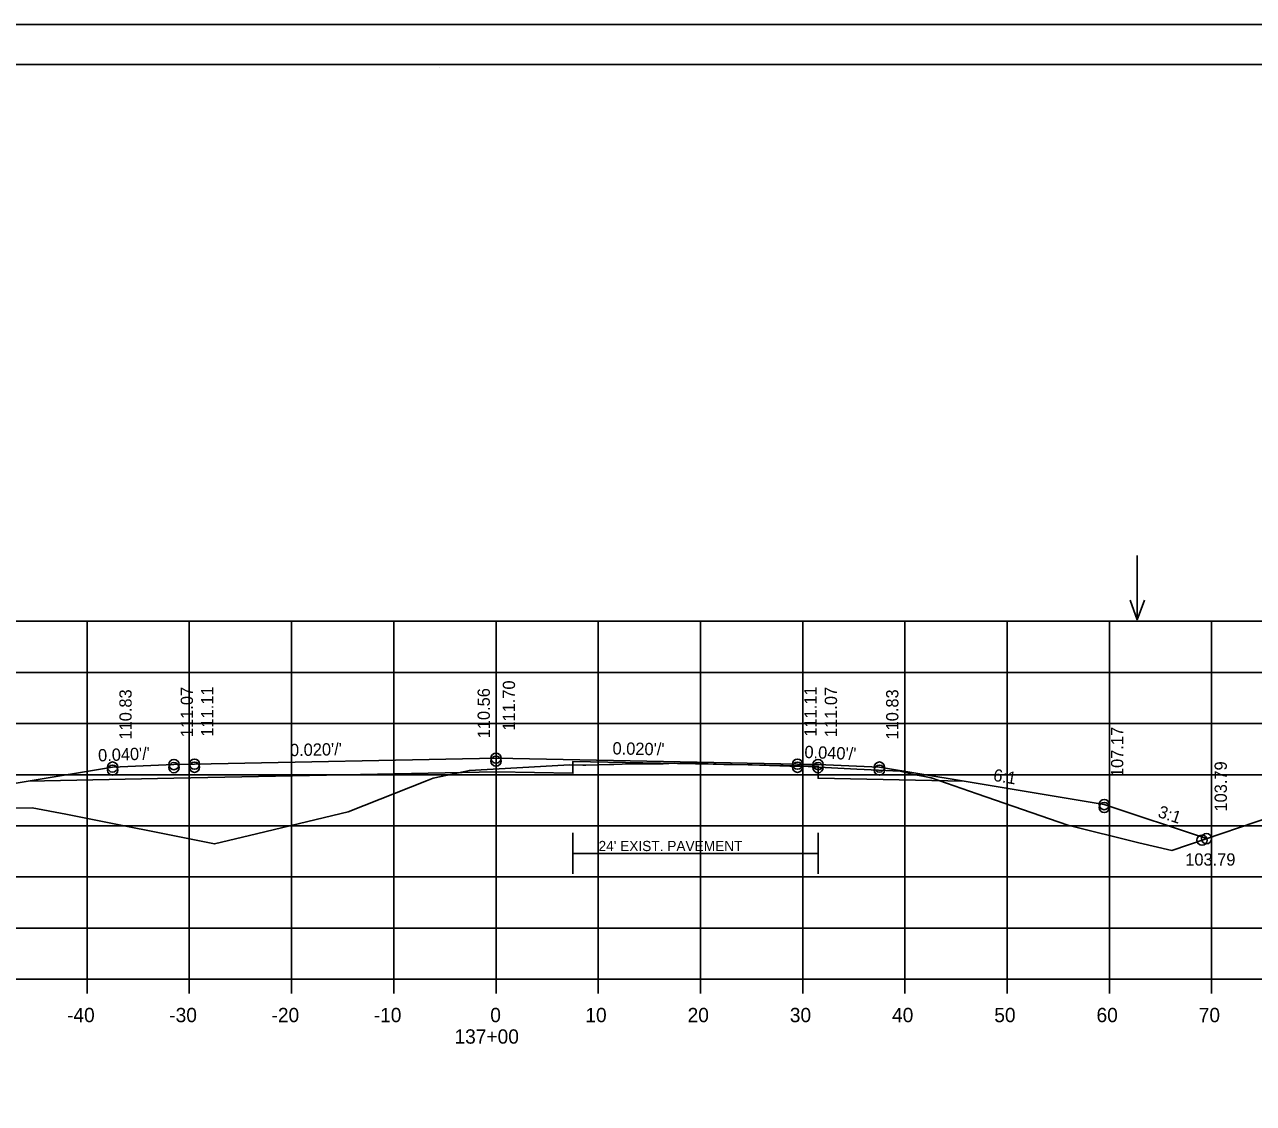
# Model space of a CAD drawing. Extents: x 1175611 to 1176402, y -433344 to -416213.
# Drawn here: x 1175734.9 to 1175855.1, y -430249 to -430143.5 of the extents above; entities that cross this region are included whole.
import ezdxf

# ---------------------------------------------------------------- set-up
doc = ezdxf.new("R2010")
doc.units = 0
for name, color, linetype in [('R_Alt Surface', 7, 'Continuous'), ('R_Axis', 7, 'Continuous'), ('R_Axis Annot', 7, 'Continuous'), ('R_Border', 7, 'Continuous'), ('R_Draft', 7, 'Continuous'), ('R_Exist Surface', 7, 'Continuous'), ('R_Fin Surface', 7, 'Continuous'), ('R_Grid', 7, 'Continuous'), ('R_No Plot', 7, 'Continuous'), ('R_Water Annot', 7, 'Continuous'), ('R_Xsect Elev', 7, 'Continuous'), ('R_Xsect Slope', 7, 'Continuous')]:
    doc.layers.add(name, color=color, linetype=linetype)

msp = doc.modelspace()

# ---------------------------------------------------------------- linework, layer by layer
at = {"layer": 'R_Alt Surface'}
msp.add_lwpolyline([(1175735.2, -430217.45), (1175749.47, -430217.17), (1175780.97, -430216.53), (1175788.49, -430216.68), (1175788.49, -430215.52), (1175812.49, -430216), (1175812.47, -430217.17), (1175826.75, -430217.45)], dxfattribs=at)
at = {"layer": 'R_Axis'}
for p, q in [((1175640.97, -430236.82), (1175920.97, -430236.82)), ((1175740.97, -430238.22), (1175740.97, -430236.82)), ((1175750.97, -430238.22), (1175750.97, -430236.82)), ((1175760.97, -430238.22), (1175760.97, -430236.82)), ((1175770.97, -430238.22), (1175770.97, -430236.82)), ((1175780.97, -430238.22), (1175780.97, -430236.82)), ((1175790.97, -430238.22), (1175790.97, -430236.82)), ((1175800.97, -430238.22), (1175800.97, -430236.82)), ((1175810.97, -430238.22), (1175810.97, -430236.82)), ((1175820.97, -430238.22), (1175820.97, -430236.82)), ((1175830.97, -430238.22), (1175830.97, -430236.82)), ((1175840.97, -430238.22), (1175840.97, -430236.82)), ((1175850.97, -430238.22), (1175850.97, -430236.82))]:
    msp.add_line(p, q, dxfattribs=at)
at = {"layer": 'R_Border'}
for p, q in [((1175622.97, -430147.36), (1175939.15, -430147.36)), ((1175775.49, -430147.62), (1175775.49, -430147.62)), ((1175775.49, -430147.62), (1175775.49, -430147.62))]:
    msp.add_line(p, q, dxfattribs=at)
at = {"layer": 'R_Draft'}
for q in [(1175788.49, -430224.51), (1175812.49, -430224.51)]:
    msp.add_line((1175800.49, -430224.51), q, dxfattribs=at)
for points in [[(1175788.49, -430226.51), (1175788.49, -430222.51)], [(1175812.49, -430226.51), (1175812.49, -430222.51)]]:
    msp.add_lwpolyline(points, dxfattribs=at)
at = {"layer": 'R_Exist Surface'}
msp.add_lwpolyline([(1175690.55, -430220.08), (1175735.61, -430220.06), (1175738.89, -430220.67), (1175753.43, -430223.58), (1175756.85, -430222.78), (1175766.52, -430220.46), (1175774.17, -430217.43), (1175774.83, -430217.16), (1175775.59, -430217), (1175777.76, -430216.53), (1175778.37, -430216.4), (1175780.12, -430216.31), (1175784.18, -430216.08), (1175788.16, -430215.85), (1175789.46, -430215.88), (1175789.77, -430215.89), (1175792.08, -430215.82), (1175792.5, -430215.81), (1175793.32, -430215.8), (1175797.1, -430215.75), (1175797.31, -430215.74), (1175798.46, -430215.7), (1175798.71, -430215.71), (1175799.53, -430215.71), (1175800.68, -430215.73), (1175800.97, -430215.73), (1175803.27, -430215.81), (1175803.77, -430215.82), (1175804.06, -430215.82), (1175806.03, -430215.85), (1175806.76, -430215.88), (1175809.7, -430215.97), (1175809.96, -430215.97), (1175810.98, -430215.99), (1175812.54, -430216.07), (1175816.28, -430216.27), (1175820.49, -430216.48), (1175821.82, -430216.79), (1175822.9, -430217.01), (1175823.54, -430217.14), (1175828.03, -430218.69), (1175836.9, -430221.77), (1175843.86, -430223.47), (1175847.09, -430224.22), (1175858.58, -430220.33)], dxfattribs=at)
at = {"layer": 'R_Fin Surface'}
msp.add_lwpolyline([(1175686.73, -430220.07), (1175703.6, -430225.7), (1175721.47, -430219.74), (1175735.2, -430217.45), (1175743.47, -430216.07), (1175749.47, -430215.83), (1175751.47, -430215.79), (1175780.97, -430215.2), (1175810.47, -430215.79), (1175812.47, -430215.83), (1175818.47, -430216.07), (1175826.75, -430217.45), (1175840.47, -430219.74), (1175850.47, -430223.07)], dxfattribs=at)
msp.add_lwpolyline([(1175686.73, -430220.07), (1175703.6, -430225.7), (1175721.47, -430219.74), (1175735.2, -430217.45), (1175743.47, -430216.07), (1175749.47, -430215.83), (1175751.47, -430215.79), (1175780.97, -430215.2), (1175810.47, -430215.79), (1175812.47, -430215.83), (1175818.47, -430216.07), (1175826.75, -430217.45), (1175840.47, -430219.74), (1175850.47, -430223.07)], dxfattribs=at)
at = {"layer": 'R_Grid'}
for p, q in [((1175640.97, -430201.82), (1175920.97, -430201.82)), ((1175740.97, -430236.82), (1175740.97, -430201.82)), ((1175750.97, -430236.82), (1175750.97, -430201.82)), ((1175760.97, -430236.82), (1175760.97, -430201.82)), ((1175770.97, -430236.82), (1175770.97, -430201.82)), ((1175780.97, -430236.82), (1175780.97, -430201.82)), ((1175790.97, -430236.82), (1175790.97, -430201.82)), ((1175800.97, -430236.82), (1175800.97, -430201.82)), ((1175810.97, -430236.82), (1175810.97, -430201.82)), ((1175820.97, -430236.82), (1175820.97, -430201.82)), ((1175830.97, -430236.82), (1175830.97, -430201.82)), ((1175840.97, -430236.82), (1175840.97, -430201.82)), ((1175850.97, -430236.82), (1175850.97, -430201.82)), ((1175640.97, -430206.82), (1175920.97, -430206.82)), ((1175640.97, -430211.82), (1175920.97, -430211.82)), ((1175640.97, -430216.82), (1175920.97, -430216.82)), ((1175640.97, -430221.82), (1175920.97, -430221.82)), ((1175640.97, -430226.82), (1175920.97, -430226.82)), ((1175640.97, -430231.82), (1175920.97, -430231.82)), ((1175640.97, -430236.82), (1175920.97, -430236.82))]:
    msp.add_line(p, q, dxfattribs=at)
at = {"layer": 'R_No Plot'}
msp.add_line((1175610.57, -430143.46), (1175943.91, -430143.46), dxfattribs=at)
msp.add_lwpolyline([(1175610.57, -430143.46), (1175943.91, -430143.46), (1175943.91, -430356.8), (1175610.57, -430356.8)], close=True, dxfattribs=at)
for centre in [(1175743.47, -430216.07), (1175749.47, -430215.83), (1175751.47, -430215.79), (1175751.47, -430216.09), (1175780.97, -430215.2), (1175780.97, -430215.5), (1175810.47, -430215.79), (1175810.47, -430216.09), (1175812.47, -430215.83), (1175818.47, -430216.07), (1175743.47, -430216.37), (1175749.47, -430216.13), (1175812.47, -430216.13), (1175818.47, -430216.37), (1175840.47, -430219.74), (1175840.47, -430220.03), (1175850.03, -430223.22), (1175850.47, -430223.07), (1175850.47, -430223.07)]:
    msp.add_circle(centre, 0.5, dxfattribs=at)
at = {"layer": 'R_Water Annot'}
for p, q in [((1175843.7, -430195.39), (1175843.7, -430201.67)), ((1175843.7, -430201.67), (1175843, -430199.75)), ((1175843.7, -430201.67), (1175844.4, -430199.75))]:
    msp.add_line(p, q, dxfattribs=at)

# ---------------------------------------------------------------- texts
at = {"layer": 'R_Axis Annot'}
for s, p in [('-40', (1175739.01, -430241.02)), ('-30', (1175749.01, -430241.02)), ('-20', (1175759.01, -430241.02)), ('-10', (1175769.01, -430241.02)), ('0', (1175780.41, -430241.02)), ('10', (1175789.71, -430241.02)), ('20', (1175799.71, -430241.02)), ('30', (1175809.71, -430241.02)), ('40', (1175819.71, -430241.02)), ('50', (1175829.71, -430241.02)), ('60', (1175839.71, -430241.02)), ('70', (1175849.71, -430241.02)), ('137+00', (1175776.91, -430243.12))]:
    msp.add_text(s, height=1.4, dxfattribs=at).set_placement(p)
at = {"layer": 'R_Draft'}
msp.add_text("24' EXIST. PAVEMENT", height=1, dxfattribs=at).set_placement((1175791, -430224.29))
at = {"layer": 'R_Xsect Elev'}
for s, p in [('111.07', (1175751.33, -430213.14)), ('111.11', (1175753.33, -430213.1)), ('111.70', (1175782.83, -430212.51)), ('111.11', (1175812.33, -430213.1)), ('111.07', (1175814.33, -430213.14)), ('110.83', (1175745.33, -430213.38)), ('110.56', (1175780.37, -430213.26)), ('110.83', (1175820.33, -430213.38)), ('107.17', (1175842.33, -430217.05)), ('103.79', (1175852.46, -430220.42))]:
    msp.add_text(s, height=1.2, rotation=90, dxfattribs=at).set_placement(p)
msp.add_text('103.79', height=1.2, dxfattribs=at).set_placement((1175848.39, -430225.71))
at = {"layer": 'R_Xsect Slope'}
for s, rotation, p in [("0.040'/'", 2.2906, (1175742.07, -430215.53)), ("0.020'/'", 1.1458, (1175760.83, -430215.01)), ("0.020'/'", 358.8542, (1175792.36, -430214.83)), ("0.040'/'", 357.7094, (1175811.12, -430215.18)), ('6:1', 350.5377, (1175829.55, -430217.41)), ('3:1', 341.5651, (1175845.63, -430220.93))]:
    msp.add_text(s, height=1.2, rotation=rotation, dxfattribs=at).set_placement(p)

doc.saveas('drawing.dxf')
